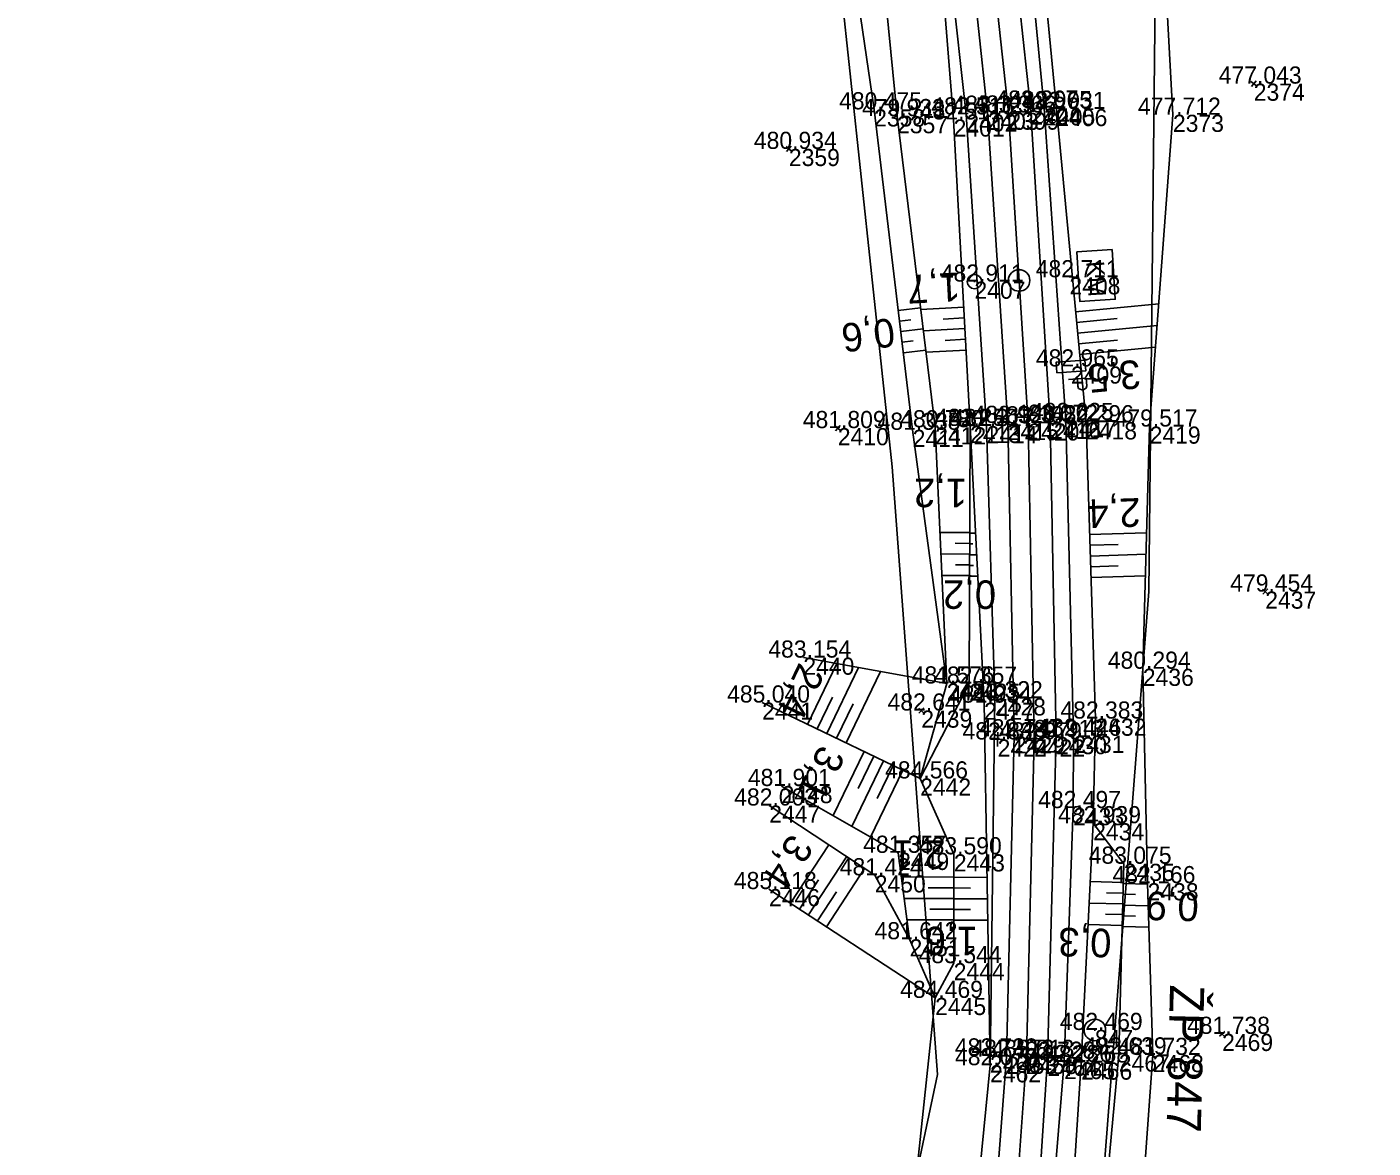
# Model space of a CAD drawing. Extents: x -1234191 to 23050, y -1290331 to -741191.
# Drawn here: x -865097.3 to -865003.1, y -1108278.9 to -1108200.5 of the extents above; entities that cross this region are included whole.
import ezdxf

# ---------------------------------------------------------------- set-up
doc = ezdxf.new("R2010")
doc.units = 0
for name, color, linetype in [('Vrstva 1', 7, 'Continuous'), ('Vrstva 33', 7, 'Continuous'), ('Vrstva 4', 7, 'Continuous'), ('Vrstva 48', 7, 'Continuous'), ('Vrstva 49', 7, 'Continuous'), ('Vrstva 53', 7, 'Continuous'), ('Vrstva 60', 7, 'Continuous'), ('Vrstva 61', 7, 'Continuous'), ('Vrstva 63', 7, 'Continuous'), ('Vrstva 7', 7, 'Continuous')]:
    doc.layers.add(name, color=color, linetype=linetype)

msp = doc.modelspace()

# ---------------------------------------------------------------- linework, layer by layer
at = {"layer": 'Vrstva 1'}
msp.add_lwpolyline([(-865030.656, -1108187.291), (-865028.588, -1108206.453), (-865027.191, -1108228.212), (-865026.787, -1108250.334), (-865027.323, -1108272.555), (-865028.878, -1108294.436), (-865031.68, -1108318.454), (-865035.254, -1108342.066), (-865039.426, -1108365.738), (-865043.869, -1108389.362), (-865053.202, -1108438.524), (-865059.715, -1108472.613), (-865066.083, -1108505.937), (-865070.141, -1108527.603), (-865073.945, -1108549.688), (-865077.058, -1108571.775)], dxfattribs=at)
at = {"layer": 'Vrstva 33'}
msp.add_lwpolyline([(-865023.224, -1108223.791), (-865023.176, -1108224.534), (-865025.186, -1108224.663), (-865025.234, -1108223.92)], close=True, dxfattribs=at)
for points in [[(-865024.389, -1108225.135), (-865023.138, -1108225.055)], [(-865023.722, -1108225.615), (-865023.756, -1108225.094)], [(-865023.138, -1108225.055), (-865023.105, -1108225.575)], [(-865023.105, -1108225.575), (-865023.147, -1108225.736), (-865023.342, -1108225.859), (-865023.453, -1108225.866), (-865023.667, -1108225.769), (-865023.722, -1108225.615)]]:
    msp.add_lwpolyline(points, dxfattribs=at)
at = {"layer": 'Vrstva 4'}
for points in [[(-865033.638, -1108187.61), (-865031.529, -1108206.589), (-865030.113, -1108228.405), (-865029.53, -1108247.455), (-865029.868, -1108273.136), (-865031.927, -1108294.219), (-865034.452, -1108318.572), (-865038.1, -1108342.199), (-865042.275, -1108364.863), (-865046.748, -1108388.958), (-865055.942, -1108439.115), (-865062.682, -1108472.074), (-865069.272, -1108506.084), (-865073.095, -1108527.179), (-865077.436, -1108549.423), (-865078.937, -1108556.464), (-865078.422, -1108560.024), (-865080.077, -1108571.108)], [(-865078.366, -1108571.587), (-865075.267, -1108549.514), (-865071.535, -1108527.342), (-865067.494, -1108505.805), (-865061.048, -1108472.307), (-865054.509, -1108438.374), (-865045.208, -1108389.299), (-865040.65, -1108365.562), (-865036.605, -1108342.013), (-865032.967, -1108318.164), (-865030.371, -1108294.325), (-865028.726, -1108272.543), (-865028.19, -1108250.114), (-865028.633, -1108228.178), (-865030.043, -1108206.47), (-865032.088, -1108187.414)], [(-865029.088, -1108187.033), (-865027.037, -1108206.108), (-865025.657, -1108228.099), (-865025.246, -1108250.166), (-865025.844, -1108272.687), (-865027.271, -1108294.633), (-865030.339, -1108318.622), (-865033.856, -1108342.388), (-865037.93, -1108365.845), (-865042.572, -1108389.784), (-865051.805, -1108438.924), (-865058.302, -1108472.804), (-865064.701, -1108506.319), (-865068.774, -1108527.817), (-865072.667, -1108549.858), (-865075.645, -1108571.889)], [(-865074.332, -1108572.132), (-865072.539, -1108560.565), (-865071.432, -1108558.586), (-865070.355, -1108550.059), (-865066.757, -1108528.061), (-865062.847, -1108506.591), (-865056.831, -1108472.949), (-865050.548, -1108439.441), (-865041.619, -1108389.91), (-865037.085, -1108366.089), (-865032.911, -1108342.492), (-865029.241, -1108318.876), (-865026.485, -1108294.668), (-865024.684, -1108272.91), (-865024.052, -1108255.138), (-865024.028, -1108250.081), (-865024.558, -1108227.977), (-865026.077, -1108206.153), (-865027.957, -1108186.689)]]:
    msp.add_lwpolyline(points, dxfattribs=at)
at = {"layer": 'Vrstva 48'}
for p, q in [((-865036.289, -1108220.301), (-865034.733, -1108220.114)), ((-865031.709, -1108220.08), (-865034.717, -1108220.242)), ((-865023.886, -1108220.395), (-865018.057, -1108219.843)), ((-865036.2, -1108221.046), (-865035.42, -1108220.952)), ((-865031.669, -1108220.829), (-865033.147, -1108220.908)), ((-865023.815, -1108221.141), (-865020.964, -1108220.872)), ((-865023.744, -1108221.888), (-865018.17, -1108221.36)), ((-865036.11, -1108221.79), (-865034.55, -1108221.603)), ((-865036.021, -1108222.535), (-865035.24, -1108222.441)), ((-865031.629, -1108221.578), (-865034.534, -1108221.734)), ((-865031.588, -1108222.327), (-865033.015, -1108222.404)), ((-865023.674, -1108222.635), (-865020.95, -1108222.377)), ((-865035.931, -1108223.28), (-865034.367, -1108223.092)), ((-865031.548, -1108223.076), (-865034.351, -1108223.227)), ((-865023.603, -1108223.381), (-865018.283, -1108222.878)), ((-865031.288, -1108235.858), (-865033.375, -1108235.851)), ((-865031.29, -1108236.608), (-865032.316, -1108236.604)), ((-865031.288, -1108235.901), (-865030.884, -1108235.902)), ((-865022.903, -1108235.997), (-865018.908, -1108235.87)), ((-865031.293, -1108237.358), (-865033.308, -1108237.351)), ((-865031.293, -1108237.401), (-865030.809, -1108237.403)), ((-865031.29, -1108236.651), (-865031.068, -1108236.652)), ((-865022.879, -1108236.747), (-865020.904, -1108236.684)), ((-865022.855, -1108237.496), (-865018.95, -1108237.372)), ((-865031.295, -1108238.108), (-865032.285, -1108238.104)), ((-865031.296, -1108238.151), (-865031.033, -1108238.152)), ((-865022.831, -1108238.246), (-865020.901, -1108238.185)), ((-865031.298, -1108238.858), (-865033.241, -1108238.851)), ((-865031.298, -1108238.901), (-865030.733, -1108238.903)), ((-865022.807, -1108238.996), (-865018.992, -1108238.874)), ((-865042.642, -1108249.277), (-865040.601, -1108245.028)), ((-865041.29, -1108249.927), (-865039.069, -1108245.305)), ((-865039.938, -1108250.577), (-865037.538, -1108245.581)), ((-865041.966, -1108249.602), (-865040.901, -1108247.384)), ((-865040.614, -1108250.252), (-865039.459, -1108247.847)), ((-865038.682, -1108251.18), (-865040.839, -1108255.669)), ((-865038.006, -1108251.505), (-865039.096, -1108253.774)), ((-865037.33, -1108251.83), (-865039.534, -1108256.417)), ((-865035.978, -1108252.48), (-865038.229, -1108257.165)), ((-865036.654, -1108252.155), (-865037.768, -1108254.473)), ((-865043.835, -1108261.796), (-865041.161, -1108257.713)), ((-865042.58, -1108262.618), (-865039.91, -1108258.541)), ((-865041.325, -1108263.44), (-865038.659, -1108259.368)), ((-865032.403, -1108259.966), (-865036.077, -1108259.96)), ((-865032.403, -1108259.982), (-865030.086, -1108259.987)), ((-865043.207, -1108262.207), (-865041.871, -1108260.167)), ((-865041.952, -1108263.029), (-865040.618, -1108260.992)), ((-865032.404, -1108260.716), (-865034.191, -1108260.713)), ((-865032.404, -1108260.732), (-865031.239, -1108260.734)), ((-865020.542, -1108260.35), (-865022.856, -1108260.289)), ((-865020.562, -1108261.1), (-865021.728, -1108261.069)), ((-865020.544, -1108260.424), (-865018.842, -1108260.468)), ((-865032.406, -1108261.466), (-865035.879, -1108261.46)), ((-865032.406, -1108261.482), (-865030.061, -1108261.487)), ((-865020.582, -1108261.849), (-865022.931, -1108261.788)), ((-865020.583, -1108261.923), (-865018.796, -1108261.97)), ((-865020.564, -1108261.174), (-865019.691, -1108261.196)), ((-865032.408, -1108262.966), (-865035.681, -1108262.96)), ((-865032.407, -1108262.216), (-865034.094, -1108262.213)), ((-865032.408, -1108262.982), (-865030.036, -1108262.987)), ((-865032.407, -1108262.232), (-865031.228, -1108262.234)), ((-865020.601, -1108262.599), (-865021.785, -1108262.568)), ((-865020.603, -1108262.673), (-865019.688, -1108262.697)), ((-865020.621, -1108263.349), (-865023.006, -1108263.286)), ((-865020.623, -1108263.423), (-865018.75, -1108263.472))]:
    msp.add_line(p, q, dxfattribs=at)
at = {"layer": 'Vrstva 49'}
for p, q in [((-865011.605, -1108204.272), (-865011.215, -1108204.586)), ((-865011.253, -1108204.234), (-865011.567, -1108204.624)), ((-865044.137, -1108208.834), (-865043.761, -1108209.164)), ((-865043.784, -1108208.811), (-865044.114, -1108209.187)), ((-865040.709, -1108228.376), (-865040.333, -1108228.706)), ((-865040.356, -1108228.353), (-865040.686, -1108228.729)), ((-865010.788, -1108239.808), (-865010.428, -1108240.156)), ((-865010.434, -1108239.802), (-865010.782, -1108240.162)), ((-865032.901, -1108246.417), (-865034.762, -1108253.064)), ((-865034.762, -1108253.064), (-865045.821, -1108247.75)), ((-865034.863, -1108248.136), (-865034.503, -1108248.484)), ((-865034.509, -1108248.13), (-865034.857, -1108248.49)), ((-865045.344, -1108260.808), (-865033.711, -1108268.425)), ((-865035.502, -1108264.32), (-865033.711, -1108268.425)), ((-865013.446, -1108270.77), (-865013.808, -1108271.114)), ((-865013.799, -1108270.761), (-865013.455, -1108271.123))]:
    msp.add_line(p, q, dxfattribs=at)
for points in [[(-865019.176, -1108245.385), (-865018.698, -1108228.432), (-865017.069, -1108206.608), (-865017.874, -1108191.985), (-865019.611, -1108187.666), (-865019.596, -1108188.437), (-865020.005, -1108188.464), (-865020.022, -1108188.203), (-865024.125, -1108187.869), (-865024.058, -1108188.483), (-865024.058, -1108188.483), (-865023.998, -1108188.476), (-865023.998, -1108188.476), (-865024.446, -1108184.37), (-865024.446, -1108184.37), (-865024.506, -1108184.377), (-865024.506, -1108184.377), (-865024.443, -1108184.95), (-865020.334, -1108183.597), (-865020.401, -1108182.813), (-865020.02, -1108182.78), (-865019.875, -1108184.12)], [(-865022.651, -1108256.198), (-865022.493, -1108248.875), (-865023.153, -1108228.133), (-865025.229, -1108206.204), (-865027.314, -1108184.355)], [(-865034.762, -1108253.064), (-865031.324, -1108246.429), (-865031.262, -1108228.387), (-865032.417, -1108206.937), (-865034.146, -1108185.382)], [(-865040.578, -1108188.523), (-865037.979, -1108206.229), (-865035.285, -1108228.661), (-865032.901, -1108246.417)], [(-865042.937, -1108244.607), (-865032.901, -1108246.417), (-865033.706, -1108228.483), (-865036.378, -1108206.704), (-865038.032, -1108189.858)], [(-865082.222, -1108559.397), (-865078.937, -1108556.464), (-865077.436, -1108549.423), (-865073.095, -1108527.179), (-865069.272, -1108506.084), (-865062.682, -1108472.074), (-865055.942, -1108439.115), (-865046.748, -1108388.958), (-865042.275, -1108364.863), (-865038.1, -1108342.199), (-865034.452, -1108318.572), (-865031.927, -1108294.219), (-865029.868, -1108273.136), (-865030.288, -1108247.759), (-865031.262, -1108228.387)], [(-865019.176, -1108245.385), (-865018.844, -1108260.395), (-865018.477, -1108272.418), (-865020.128, -1108295.394), (-865024.167, -1108319.5)], [(-865083.707, -1108556.078), (-865080.174, -1108554.33), (-865078.664, -1108548.746), (-865075.53, -1108526.601), (-865073.158, -1108505.844), (-865071.85, -1108489.687), (-865065.284, -1108437.063), (-865057.729, -1108391.14), (-865050.551, -1108362.222), (-865046.113, -1108342.687), (-865040.078, -1108316.397), (-865036.35, -1108293.318), (-865033.711, -1108268.425), (-865032.414, -1108265.993), (-865032.4, -1108258.375), (-865034.762, -1108253.064)], [(-865044.461, -1108253.594), (-865036.299, -1108258.271), (-865035.502, -1108264.32)], [(-865035.502, -1108264.32), (-865037.938, -1108259.845), (-865045.324, -1108254.96)], [(-865063.961, -1108564.433), (-865066.524, -1108559.648), (-865066.037, -1108551.072), (-865061.887, -1108528.709), (-865056.742, -1108504.347), (-865056.831, -1108472.949), (-865050.548, -1108439.441), (-865040.899, -1108390.168), (-865036.258, -1108366.166), (-865031.928, -1108342.75), (-865027.888, -1108319.288), (-865024.894, -1108294.753), (-865023.489, -1108272.95), (-865022.651, -1108256.198)], [(-865061.887, -1108528.709), (-865052.444, -1108502.461), (-865049.677, -1108466.642), (-865042.991, -1108438.223), (-865035.28, -1108403.002), (-865034.132, -1108390.359), (-865030.687, -1108366.58), (-865027.272, -1108343.329), (-865024.167, -1108319.5), (-865022.949, -1108295.008), (-865020.857, -1108272.384), (-865020.508, -1108259.036), (-865022.651, -1108256.198)]]:
    msp.add_lwpolyline(points, dxfattribs=at)
at = {"layer": 'Vrstva 53'}
for points in [[(-865097.28, -1108650.63), (-865077.79, -1108523.9), (-865062.58, -1108401.69), (-865048.74, -1108345.61), (-865033.548, -1108273.797), (-865036.719, -1108231.242), (-865042.497, -1108177.09), (-865069.37, -1108070.21), (-865060.755, -1107948.38), (-865040.047, -1107836.105), (-865031.84, -1107728.7), (-865056.26, -1107614.01)], [(-865004.69, -1107700.09), (-865003.06, -1107712.548), (-865020.95, -1107733.574), (-865021.38, -1107803.91), (-865041.945, -1107946.278), (-865044.86, -1108022.805), (-865018.158, -1108183.051), (-865018.752, -1108239.984), (-865026.02, -1108333.53), (-865033.42, -1108388.81), (-865018.239, -1108387.767), (-865021.853, -1108424.716), (-865038.93, -1108425.11), (-865057.34, -1108498.15), (-865069.183, -1108569.747)]]:
    msp.add_lwpolyline(points, dxfattribs=at)
at = {"layer": 'Vrstva 60'}
for p, q in [((-865011.41, -1108204.429), (-865011.41, -1108204.429)), ((-865037.979, -1108206.229), (-865037.979, -1108206.229)), ((-865028.588, -1108206.453), (-865028.588, -1108206.453)), ((-865027.037, -1108206.108), (-865027.037, -1108206.108)), ((-865026.077, -1108206.153), (-865026.077, -1108206.153)), ((-865025.229, -1108206.204), (-865025.229, -1108206.204)), ((-865036.378, -1108206.704), (-865036.378, -1108206.704)), ((-865032.417, -1108206.937), (-865032.417, -1108206.937)), ((-865031.529, -1108206.589), (-865031.529, -1108206.589)), ((-865030.043, -1108206.47), (-865030.043, -1108206.47)), ((-865017.069, -1108206.608), (-865017.069, -1108206.608)), ((-865043.949, -1108208.999), (-865043.949, -1108208.999)), ((-865030.961, -1108218.287), (-865030.961, -1108218.287)), ((-865024.313, -1108217.983), (-865024.313, -1108217.983)), ((-865024.205, -1108224.227), (-865024.205, -1108224.227)), ((-865025.657, -1108228.099), (-865025.657, -1108228.099)), ((-865024.558, -1108227.977), (-865024.558, -1108227.977)), ((-865040.521, -1108228.541), (-865040.521, -1108228.541)), ((-865035.285, -1108228.661), (-865035.285, -1108228.661)), ((-865033.706, -1108228.483), (-865033.706, -1108228.483)), ((-865031.262, -1108228.387), (-865031.262, -1108228.387)), ((-865030.113, -1108228.405), (-865030.113, -1108228.405)), ((-865028.633, -1108228.178), (-865028.633, -1108228.178)), ((-865027.191, -1108228.212), (-865027.191, -1108228.212)), ((-865023.153, -1108228.133), (-865023.153, -1108228.133)), ((-865018.698, -1108228.432), (-865018.698, -1108228.432)), ((-865010.608, -1108239.982), (-865010.608, -1108239.982)), ((-865042.937, -1108244.607), (-865042.937, -1108244.607)), ((-865019.176, -1108245.385), (-865019.176, -1108245.385)), ((-865032.901, -1108246.417), (-865032.901, -1108246.417)), ((-865031.324, -1108246.429), (-865031.324, -1108246.429)), ((-865045.821, -1108247.75), (-865045.821, -1108247.75)), ((-865030.288, -1108247.759), (-865030.288, -1108247.759)), ((-865029.53, -1108247.455), (-865029.53, -1108247.455)), ((-865034.683, -1108248.31), (-865034.683, -1108248.31)), ((-865022.493, -1108248.875), (-865022.493, -1108248.875)), ((-865029.339, -1108250.335), (-865029.339, -1108250.335)), ((-865028.19, -1108250.114), (-865028.19, -1108250.114)), ((-865026.787, -1108250.334), (-865026.787, -1108250.334)), ((-865025.246, -1108250.166), (-865025.246, -1108250.166)), ((-865024.028, -1108250.081), (-865024.028, -1108250.081)), ((-865034.762, -1108253.064), (-865034.762, -1108253.064)), ((-865044.461, -1108253.594), (-865044.461, -1108253.594)), ((-865045.324, -1108254.96), (-865045.324, -1108254.96)), ((-865024.052, -1108255.138), (-865024.052, -1108255.138)), ((-865022.651, -1108256.198), (-865022.651, -1108256.198)), ((-865036.299, -1108258.271), (-865036.299, -1108258.271)), ((-865032.4, -1108258.375), (-865032.4, -1108258.375)), ((-865020.508, -1108259.036), (-865020.508, -1108259.036)), ((-865037.938, -1108259.845), (-865037.938, -1108259.845)), ((-865045.344, -1108260.808), (-865045.344, -1108260.808)), ((-865018.844, -1108260.395), (-865018.844, -1108260.395)), ((-865035.502, -1108264.32), (-865035.502, -1108264.32)), ((-865032.414, -1108265.993), (-865032.414, -1108265.993)), ((-865033.711, -1108268.425), (-865033.711, -1108268.425)), ((-865022.533, -1108270.67), (-865022.533, -1108270.67)), ((-865013.627, -1108270.942), (-865013.627, -1108270.942)), ((-865020.857, -1108272.384), (-865020.857, -1108272.384)), ((-865029.879, -1108272.457), (-865029.879, -1108272.457)), ((-865029.868, -1108273.136), (-865029.868, -1108273.136)), ((-865028.726, -1108272.543), (-865028.726, -1108272.543)), ((-865027.323, -1108272.555), (-865027.323, -1108272.555)), ((-865025.844, -1108272.687), (-865025.844, -1108272.687)), ((-865024.684, -1108272.91), (-865024.684, -1108272.91)), ((-865023.489, -1108272.95), (-865023.489, -1108272.95)), ((-865018.477, -1108272.418), (-865018.477, -1108272.418))]:
    msp.add_line(p, q, dxfattribs=at)
at = {"layer": 'Vrstva 63'}
msp.add_line((-865022.532, -1108270.62), (-865022.534, -1108270.72), dxfattribs=at)
msp.add_circle((-865022.533, -1108270.67), 0.756, dxfattribs=at)
at = {"layer": 'Vrstva 7'}
for p, q in [((-865030.964, -1108218.237), (-865030.958, -1108218.337)), ((-865024.313, -1108217.983), (-865023.691, -1108217.943)), ((-865028.839, -1108250.347), (-865029.839, -1108250.323)), ((-865029.327, -1108249.835), (-865029.351, -1108250.835)), ((-865029.844, -1108271.958), (-865029.914, -1108272.956)), ((-865029.38, -1108272.492), (-865030.378, -1108272.422))]:
    msp.add_line(p, q, dxfattribs=at)
msp.add_lwpolyline([(-865023.803, -1108216.205), (-865021.325, -1108216.046), (-865021.102, -1108219.526), (-865023.579, -1108219.685)], close=True, dxfattribs=at)
for centre, radius in [((-865027.833, -1108218.209), 0.75), ((-865030.961, -1108218.287), 0.5)]:
    msp.add_circle(centre, radius, dxfattribs=at)

# ---------------------------------------------------------------- texts
at = {"layer": 'Vrstva 48'}
for s, rotation, p in [('1,7', 183.08218, (-865032.012, -1108217.641)), ('0,6', 186.84821, (-865036.668, -1108220.822)), ('3,5', 185.40803, (-865019.434, -1108223.746)), ('1,2', 179.80311, (-865031.472, -1108232.085)), ('2,4', 181.82251, (-865019.369, -1108233.432)), ('0,2', 179.80311, (-865029.442, -1108239.201)), ('2,4', 244.33508, (-865043.208, -1108244.873)), ('3,1', 244.33508, (-865041.763, -1108250.619)), ('3,4', 236.78421, (-865043.806, -1108256.826)), ('2,1', 179.8947, (-865032.981, -1108257.392)), ('0,9', 178.50227, (-865015.236, -1108261.068)), ('1,6', 179.8947, (-865030.711, -1108263.446)), ('0,3', 178.50227, (-865021.346, -1108263.602))]:
    msp.add_text(s, height=2, rotation=rotation, dxfattribs=at).set_placement(p)
at = {"layer": 'Vrstva 60'}
for s, p in [('2374', (-865011.41, -1108205.629)), ('2358', (-865037.979, -1108207.429)), ('2403', (-865030.043, -1108207.67)), ('2399', (-865028.588, -1108207.653)), ('2404', (-865027.037, -1108207.308)), ('2405', (-865026.077, -1108207.353)), ('2406', (-865025.229, -1108207.404)), ('2357', (-865036.378, -1108207.904)), ('2401', (-865032.417, -1108208.137)), ('2402', (-865031.529, -1108207.789)), ('2373', (-865017.069, -1108207.808)), ('2359', (-865043.949, -1108210.199)), ('2407', (-865030.961, -1108219.487)), ('2408', (-865024.313, -1108219.183)), ('2409', (-865024.205, -1108225.427)), ('2416', (-865025.657, -1108229.299)), ('2417', (-865024.558, -1108229.177)), ('2418', (-865023.153, -1108229.333)), ('2410', (-865040.521, -1108229.741)), ('2411', (-865035.285, -1108229.861)), ('2412', (-865033.706, -1108229.683)), ('2413', (-865031.262, -1108229.587)), ('2414', (-865030.113, -1108229.605)), ('2415', (-865028.633, -1108229.378)), ('2420', (-865027.191, -1108229.412)), ('2419', (-865018.698, -1108229.632)), ('2437', (-865010.608, -1108241.182)), ('2440', (-865042.937, -1108245.807)), ('2436', (-865019.176, -1108246.585)), ('2426', (-865032.901, -1108247.617)), ('2425', (-865031.324, -1108247.629)), ('2441', (-865045.821, -1108248.95)), ('2427', (-865030.288, -1108248.959)), ('2428', (-865029.53, -1108248.655)), ('2439', (-865034.683, -1108249.51)), ('2432', (-865022.493, -1108250.075)), ('2424', (-865029.339, -1108251.535)), ('2429', (-865028.19, -1108251.314)), ('2422', (-865026.787, -1108251.534)), ('2430', (-865025.246, -1108251.366)), ('2431', (-865024.028, -1108251.281)), ('2442', (-865034.762, -1108254.264)), ('2448', (-865044.461, -1108254.794)), ('2447', (-865045.324, -1108256.16)), ('2433', (-865024.052, -1108256.338)), ('2434', (-865022.651, -1108257.398)), ('2449', (-865036.299, -1108259.471)), ('2443', (-865032.4, -1108259.575)), ('2435', (-865020.508, -1108260.236)), ('2450', (-865037.938, -1108261.045)), ('2446', (-865045.344, -1108262.008)), ('2438', (-865018.844, -1108261.595)), ('2451', (-865035.502, -1108265.52)), ('2444', (-865032.414, -1108267.193)), ('2445', (-865033.711, -1108269.625)), ('847', (-865022.533, -1108271.87)), ('2469', (-865013.627, -1108272.142)), ('2467', (-865020.857, -1108273.584)), ('2468', (-865018.477, -1108273.618)), ('2460', (-865029.879, -1108273.657)), ('2462', (-865029.868, -1108274.336)), ('2463', (-865028.726, -1108273.743)), ('2458', (-865027.323, -1108273.755)), ('2464', (-865025.844, -1108273.887)), ('2465', (-865024.684, -1108274.11)), ('2466', (-865023.489, -1108274.15))]:
    msp.add_text(s, height=1.2, dxfattribs=at).set_placement(p)
at = {"layer": 'Vrstva 61'}
for s, p in [('477.043', (-865013.862, -1108204.429)), ('480.475', (-865040.435, -1108206.229)), ('479.933', (-865038.83, -1108206.704)), ('482.516', (-865033.981, -1108206.589)), ('483.125', (-865032.499, -1108206.47)), ('483.366', (-865031.04, -1108206.453)), ('483.267', (-865029.489, -1108206.108)), ('482.965', (-865028.533, -1108206.153)), ('482.931', (-865027.586, -1108206.204)), ('477.712', (-865019.517, -1108206.608)), ('482.511', (-865034.774, -1108206.937)), ('480.934', (-865046.4, -1108208.999)), ('482.711', (-865026.67, -1108217.983)), ('482.911', (-865033.318, -1108218.287)), ('482.965', (-865026.661, -1108224.227)), ('482.250', (-865033.713, -1108228.387)), ('482.317', (-865032.565, -1108228.405)), ('482.928', (-865031.087, -1108228.178)), ('483.162', (-865029.639, -1108228.212)), ('483.072', (-865028.105, -1108228.099)), ('482.625', (-865027.014, -1108227.977)), ('482.296', (-865025.605, -1108228.133)), ('481.809', (-865042.975, -1108228.541)), ('481.338', (-865037.739, -1108228.661)), ('480.780', (-865036.157, -1108228.483)), ('479.517', (-865021.15, -1108228.432)), ('479.454', (-865013.059, -1108239.982)), ('483.154', (-865045.388, -1108244.607)), ('480.294', (-865021.627, -1108245.385)), ('481.576', (-865035.353, -1108246.417)), ('482.357', (-865033.776, -1108246.429)), ('485.040', (-865048.272, -1108247.75)), ('481.934', (-865032.739, -1108247.759)), ('482.322', (-865031.978, -1108247.455)), ('482.641', (-865037.04, -1108248.31)), ('482.383', (-865024.945, -1108248.875)), ('482.838', (-865031.793, -1108250.335)), ('482.747', (-865030.642, -1108250.114)), ('482.979', (-865029.241, -1108250.334)), ('482.913', (-865027.698, -1108250.166)), ('482.446', (-865026.48, -1108250.081)), ('481.901', (-865046.818, -1108253.594)), ('484.566', (-865037.214, -1108253.064)), ('482.003', (-865047.776, -1108254.96)), ('482.497', (-865026.504, -1108255.138)), ('482.939', (-865025.105, -1108256.198)), ('481.357', (-865038.751, -1108258.271)), ('483.590', (-865034.851, -1108258.375)), ('483.075', (-865022.964, -1108259.036)), ('481.424', (-865040.389, -1108259.845)), ('482.166', (-865021.296, -1108260.395)), ('485.118', (-865047.798, -1108260.808)), ('481.642', (-865037.95, -1108264.32)), ('483.544', (-865034.865, -1108265.993)), ('484.469', (-865036.165, -1108268.425)), ('482.469', (-865024.987, -1108270.67)), ('481.738', (-865016.081, -1108270.942)), ('482.730', (-865032.33, -1108272.457)), ('482.573', (-865031.178, -1108272.543)), ('482.813', (-865029.775, -1108272.555)), ('482.728', (-865028.298, -1108272.687)), ('482.639', (-865023.311, -1108272.384)), ('481.732', (-865020.925, -1108272.418)), ('482.070', (-865032.319, -1108273.136)), ('482.286', (-865027.136, -1108272.91)), ('482.268', (-865025.943, -1108272.95))]:
    msp.add_text(s, height=1.2, dxfattribs=at).set_placement(p)
at = {"layer": 'Vrstva 63'}
msp.add_text('ŽP 847', height=2.4, rotation=268.61822, dxfattribs=at).set_placement((-865017.269, -1108267.477))
at = {"layer": 'Vrstva 7'}
msp.add_text('KM', height=1.2469, rotation=273.67354, dxfattribs=at).set_placement((-865023.139, -1108216.889))

doc.saveas('drawing.dxf')
